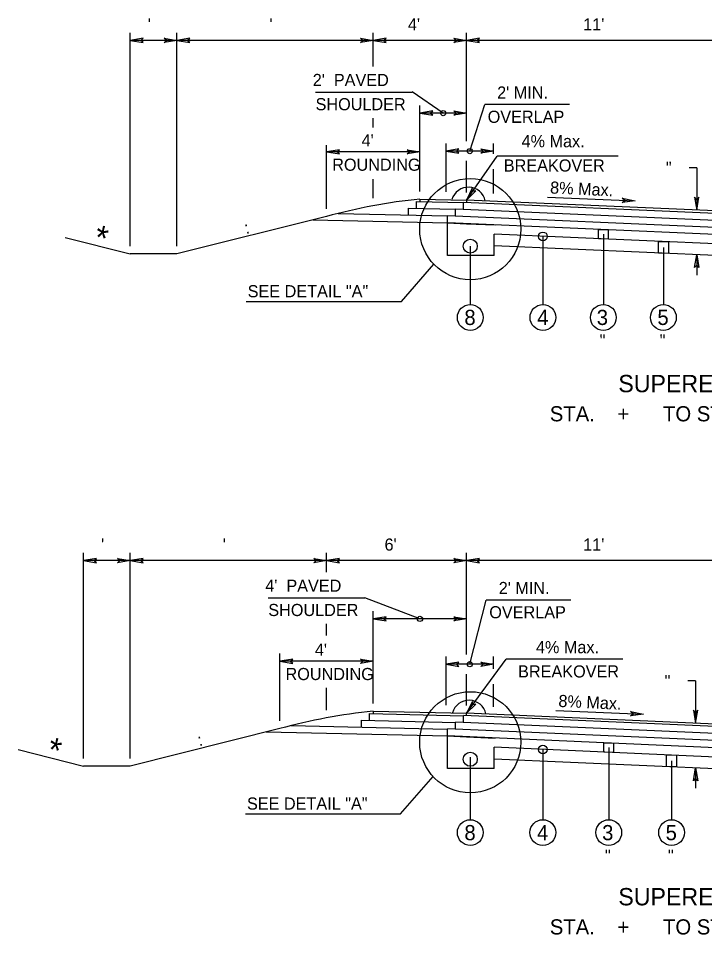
# Model space of a CAD drawing. Extents: x -592 to 1199, y -590 to 416.
# Drawn here: x 735.1 to 814.3, y 160.9 to 266.7 of the extents above; entities that cross this region are included whole.
import ezdxf

# ---------------------------------------------------------------- set-up
doc = ezdxf.new("R2010")
doc.units = 0
doc.layers.add('1', color=7, linetype='Continuous')
doc.layers.add('Des_ Drain_ Ftrs', color=7, linetype='Continuous')

msp = doc.modelspace()

# ---------------------------------------------------------------- linework, layer by layer
at = {"layer": '1'}
for p, q in [((747.99, 240.4), (747.99, 265.03)), ((753.38, 240.4), (753.38, 265.03)), ((776.04, 261.16), (776.04, 265.03)), ((786.81, 252.51), (786.81, 265.03)), ((753.38, 264.15), (747.99, 264.15)), ((776.04, 264.15), (753.38, 264.15)), ((786.81, 264.15), (776.04, 264.15)), ((816.45, 264.15), (786.81, 264.15)), ((769.38, 258.19), (780.52, 258.19)), ((784.12, 255.76), (780.53, 258.21)), ((781.43, 246.73), (781.43, 256.64)), ((787.18, 251.38), (788.92, 256.74)), ((798.68, 256.74), (788.92, 256.74)), ((776.04, 254.11), (776.04, 255.18)), ((786.81, 255.76), (781.43, 255.76)), ((770.65, 244.72), (770.65, 252.06)), ((784.44, 246.66), (784.44, 252.26)), ((789.92, 251.05), (789.92, 252.26)), ((781.43, 251.3), (770.65, 251.3)), ((789.92, 251.38), (784.44, 251.38)), ((786.81, 245.73), (790.36, 250.79)), ((804.31, 250.79), (790.36, 250.79)), ((786.81, 246.61), (786.81, 250.25)), ((789.92, 246.48), (789.92, 249.29)), ((813.39, 249.45), (812.51, 249.45)), ((813.39, 249.45), (813.39, 244.57)), ((776.04, 245.95), (776.04, 248.13)), ((781.04, 245.56), (786.47, 245.45)), ((781.04, 244.78), (781.04, 245.56)), ((781.43, 245.85), (786.81, 245.73)), ((781.43, 245.85), (781.43, 245.55)), ((816.45, 244.14), (786.47, 245.45)), ((786.47, 244.64), (786.47, 245.45)), ((816.45, 244.44), (786.81, 245.73)), ((786.81, 245.73), (786.81, 245.43)), ((796.15, 246.08), (806.26, 245.64)), ((780.11, 244.8), (785.55, 244.68)), ((780.11, 244.01), (780.11, 244.8)), ((816.45, 243.33), (785.55, 244.68)), ((785.55, 243.87), (785.55, 244.68)), ((770.65, 243.84), (753.38, 239.52)), ((769.06, 243.44), (784.62, 243.1)), ((771.97, 244.18), (784.62, 243.91)), ((816.45, 242.52), (784.62, 243.91)), ((784.62, 243.1), (784.62, 243.91)), ((784.62, 239.34), (784.62, 243.1)), ((784.62, 243.1), (786.81, 243)), ((816.45, 241.71), (784.64, 243.1)), ((786.81, 243), (790.11, 242.86)), ((740.46, 241.4), (747.99, 239.52)), ((816.45, 240.63), (790.01, 241.79)), ((790.01, 239.34), (790.01, 241.79)), ((795.63, 241.54), (795.63, 233.67)), ((802.6, 241.78), (802.6, 233.67)), ((787.24, 240.65), (787.24, 240.65)), ((787.24, 240.41), (787.24, 233.67)), ((816.45, 239.28), (790.01, 240.44)), ((809.53, 240.26), (809.53, 233.67)), ((753.38, 239.52), (747.99, 239.52)), ((790.01, 239.34), (784.62, 239.34)), ((813.39, 239.42), (813.39, 237.05)), ((779.29, 234.01), (783.02, 238.33)), ((761.35, 234.01), (779.29, 234.01)), ((742.6, 181.29), (742.6, 205)), ((747.98, 204.12), (742.6, 204.12)), ((747.98, 181.29), (747.98, 205)), ((770.65, 204.12), (747.98, 204.12)), ((770.65, 202.79), (770.65, 205)), ((786.81, 204.12), (770.65, 204.12)), ((786.81, 193.29), (786.81, 205)), ((816.45, 204.12), (786.81, 204.12)), ((763.92, 199.82), (775.06, 199.82)), ((781.43, 197.39), (775.06, 199.82)), ((787.18, 192.16), (789.09, 199.56)), ((798.86, 199.56), (789.09, 199.56)), ((776.04, 187.63), (776.04, 198.27)), ((770.65, 195.47), (770.65, 196.83)), ((786.81, 197.39), (776.04, 197.39)), ((765.26, 185.62), (765.26, 193.39)), ((776.04, 192.51), (765.26, 192.51)), ((784.44, 187.44), (784.44, 193.04)), ((786.81, 186.51), (791.39, 192.73)), ((789.92, 191.62), (789.92, 193.04)), ((804.87, 192.73), (791.39, 192.73)), ((789.92, 192.16), (784.44, 192.16)), ((786.81, 187.39), (786.81, 191.03)), ((770.65, 186.85), (770.65, 189.45)), ((789.92, 187.25), (789.92, 189.85)), ((813.25, 190.24), (812.37, 190.24)), ((813.25, 190.24), (813.25, 185.36)), ((775.61, 186.46), (786.46, 186.22)), ((775.61, 185.67), (775.61, 186.46)), ((776.04, 186.75), (786.81, 186.51)), ((776.04, 186.75), (776.04, 186.45)), ((816.45, 184.92), (786.47, 186.23)), ((786.47, 185.42), (786.47, 186.23)), ((816.45, 185.22), (786.81, 186.51)), ((786.81, 186.21), (786.81, 186.51)), ((797.11, 186.82), (807.22, 186.38)), ((766.56, 185.08), (784.58, 184.68)), ((774.68, 185.69), (785.52, 185.45)), ((774.68, 184.9), (774.68, 185.69)), ((816.45, 184.11), (785.55, 185.46)), ((785.55, 184.65), (785.55, 185.46)), ((765.26, 184.74), (747.98, 180.41)), ((763.67, 184.34), (784.62, 183.88)), ((816.45, 183.3), (784.62, 184.69)), ((784.62, 183.88), (784.62, 184.69)), ((816.45, 182.49), (784.62, 183.88)), ((784.62, 180.12), (784.62, 183.88)), ((784.62, 183.88), (786.81, 183.78)), ((786.81, 183.78), (790.11, 183.64)), ((735.06, 182.3), (742.6, 180.41)), ((816.45, 181.41), (790.01, 182.57)), ((790.01, 180.12), (790.01, 182.57)), ((795.62, 182.32), (795.62, 174.21)), ((803.22, 182.56), (803.22, 174.21)), ((787.24, 181.43), (787.24, 181.43)), ((787.24, 181.43), (787.24, 174.21)), ((816.45, 180.06), (790.01, 181.22)), ((810.48, 181), (810.48, 174.21)), ((747.98, 180.41), (742.6, 180.41)), ((790.01, 180.12), (784.62, 180.12)), ((813.25, 180.2), (813.25, 177.84)), ((779.2, 174.88), (782.94, 179.2)), ((761.27, 174.88), (779.2, 174.88))]:
    msp.add_line(p, q, dxfattribs=at)
for points in [[(802.03, 242.34), (803.17, 242.29), (803.17, 241.21), (802.03, 241.26)], [(808.96, 240.96), (810.11, 240.91), (810.11, 239.56), (808.96, 239.61)], [(802.64, 183.09), (803.79, 183.04), (803.79, 181.96), (802.64, 182.01)], [(809.91, 181.7), (811.06, 181.65), (811.06, 180.3), (809.91, 180.35)]]:
    msp.add_lwpolyline(points, close=True, dxfattribs=at)
for centre, radius in [((784.12, 255.76), 0.3), ((787.18, 251.38), 0.3), ((787.24, 242.37), 5.84), ((787.24, 240.41), 0.808), ((795.63, 241.54), 0.5), ((787.24, 232.18), 1.49), ((795.63, 232.18), 1.49), ((802.6, 232.18), 1.49), ((809.53, 232.18), 1.49), ((781.43, 197.39), 0.3), ((787.18, 192.16), 0.3), ((787.24, 183.15), 5.84), ((787.24, 181.19), 0.808), ((795.62, 182.32), 0.5), ((787.24, 172.73), 1.49), ((795.62, 172.73), 1.49), ((803.22, 172.73), 1.49), ((810.48, 172.73), 1.49)]:
    msp.add_circle(centre, radius, dxfattribs=at)
for centre, radius, start, end in [((787.02, 245.21), 2, 12.2495, 163.1706), ((788.32, 179.01), 67.19, 95.8901, 105.2487), ((787.09, 186), 2, 12.083, 163.9225), ((782.93, 119.91), 67.19, 95.8911, 105.2497)]:
    msp.add_arc(centre, radius, start, end, dxfattribs=at)
at = {"layer": 'Des_ Drain_ Ftrs'}
for points in [[(747.99, 264.15), (749.48, 263.9), (749.19, 264.15), (749.48, 264.4)], [(753.38, 264.15), (751.89, 263.9), (752.19, 264.15), (751.89, 264.4)], [(753.38, 264.15), (754.87, 263.9), (754.57, 264.15), (754.87, 264.4)], [(776.04, 264.15), (774.55, 263.9), (774.84, 264.15), (774.55, 264.4)], [(776.04, 264.15), (777.53, 263.9), (777.23, 264.15), (777.53, 264.4)], [(786.81, 264.15), (785.33, 263.9), (785.62, 264.15), (785.33, 264.4)], [(786.81, 264.15), (788.3, 263.9), (788.01, 264.15), (788.3, 264.4)], [(781.43, 255.76), (782.91, 255.51), (782.62, 255.76), (782.91, 256.01)], [(786.81, 255.76), (785.33, 255.51), (785.62, 255.76), (785.33, 256.01)], [(770.65, 251.3), (772.14, 251.05), (771.84, 251.3), (772.14, 251.54)], [(781.43, 251.3), (779.94, 251.05), (780.23, 251.3), (779.94, 251.54)], [(784.44, 251.38), (785.93, 251.13), (785.63, 251.38), (785.93, 251.63)], [(789.92, 251.38), (788.44, 251.13), (788.73, 251.38), (788.44, 251.63)], [(786.81, 245.73), (787.87, 246.81), (787.5, 246.71), (787.46, 247.09)], [(806.26, 245.64), (804.76, 245.45), (805.07, 245.69), (804.79, 245.95)], [(813.39, 244.57), (813.64, 246.06), (813.39, 245.76), (813.14, 246.06)], [(813.39, 239.42), (813.64, 237.93), (813.39, 238.23), (813.14, 237.93)], [(742.6, 204.12), (744.08, 203.87), (743.79, 204.12), (744.08, 204.37)], [(747.98, 204.12), (746.5, 203.87), (746.79, 204.12), (746.5, 204.37)], [(747.98, 204.12), (749.47, 203.87), (749.18, 204.12), (749.47, 204.37)], [(770.65, 204.12), (769.16, 203.87), (769.46, 204.12), (769.16, 204.37)], [(770.65, 204.12), (772.14, 203.87), (771.84, 204.12), (772.14, 204.37)], [(786.81, 204.12), (785.33, 203.87), (785.62, 204.12), (785.33, 204.37)], [(786.81, 204.12), (788.3, 203.87), (788.01, 204.12), (788.3, 204.37)], [(776.04, 197.39), (777.53, 197.15), (777.23, 197.39), (777.53, 197.64)], [(786.81, 197.39), (785.33, 197.15), (785.62, 197.39), (785.33, 197.64)], [(765.26, 192.51), (766.75, 192.26), (766.45, 192.51), (766.75, 192.76)], [(776.04, 192.51), (774.55, 192.26), (774.84, 192.51), (774.55, 192.76)], [(784.44, 192.16), (785.93, 191.91), (785.63, 192.16), (785.93, 192.41)], [(789.92, 192.16), (788.44, 191.91), (788.73, 192.16), (788.44, 192.41)], [(786.81, 186.51), (787.89, 187.56), (787.52, 187.47), (787.49, 187.86)], [(807.22, 186.38), (805.72, 186.2), (806.03, 186.43), (805.75, 186.69)], [(813.25, 185.36), (813.5, 186.84), (813.25, 186.55), (813, 186.84)], [(813.25, 180.2), (813.5, 178.72), (813.25, 179.01), (813, 178.72)]]:
    msp.add_lwpolyline(points, close=True, dxfattribs=at)

# ---------------------------------------------------------------- texts
at = {"layer": '1'}
for s, height, p in [(" '", 1.4, (749.49, 265.3)), ("  '", 1.4, (763.01, 265.3)), ("4'", 1.4, (780.04, 265.3)), ("11'", 1.4, (800.28, 265.3)), ("2'  PAVED", 1.4, (769.05, 258.89)), ("2' MIN.", 1.4, (790.34, 257.44)), ('SHOULDER', 1.4, (769.38, 256.09)), ('OVERLAP', 1.4, (789.25, 254.64)), ("4'", 1.4, (774.69, 251.91)), ('4% Max.', 1.4, (793.16, 251.82)), ('ROUNDING', 1.4, (771.3, 249.11)), ('BREAKOVER', 1.4, (791.11, 249.02)), ('SEE DETAIL "A"', 1.4, (761.54, 234.51)), ('8', 1.75, (786.56, 231.31)), ('4', 1.75, (794.96, 231.31)), ('3', 1.75, (801.84, 231.31)), ('5', 1.75, (808.84, 231.31)), (' "', 1.4, (801.66, 228.82)), (' "', 1.4, (808.59, 228.82)), ('SUPERELEVATED', 2, (804.33, 223.55)), ('STA.    +      TO STA.    +     ', 1.75, (796.42, 220.19)), (" '", 1.4, (744.09, 205.27)), ("  '", 1.4, (757.62, 205.27)), ("6'", 1.4, (777.34, 205.27)), ("11'", 1.4, (800.28, 205.27)), ("4'  PAVED", 1.4, (763.57, 200.52)), ("2' MIN.", 1.4, (790.52, 200.26)), ('SHOULDER', 1.4, (763.92, 197.72)), ('OVERLAP', 1.4, (789.43, 197.46)), ('4% Max.', 1.4, (794.82, 193.43)), ("4'", 1.4, (769.3, 193.13)), ('ROUNDING', 1.4, (765.91, 190.33)), ('BREAKOVER', 1.4, (792.76, 190.63)), ('SEE DETAIL "A"', 1.4, (761.46, 175.38)), ('8', 1.75, (786.56, 171.85)), ('4', 1.75, (794.95, 171.85)), ('3', 1.75, (802.46, 171.85)), ('5', 1.75, (809.79, 171.85)), (' "', 1.4, (802.27, 169.37)), (' "', 1.4, (809.54, 169.37)), ('SUPERELEVATED', 2, (804.33, 164.33)), ('STA.    +      TO STA.    +     ', 1.75, (796.42, 160.97))]:
    msp.add_text(s, height=height, dxfattribs=at).set_placement(p)
for s, height, rotation, p in [('  "', 1.4, 0.1438, (808.78, 248.75)), ('8% Max.', 1.4, 357.3765, (796.43, 246.49)), ('*', 2.8, 347.1521, (743.62, 240.17)), (' : ', 1.4, 14.2282, (760.84, 241.67)), ('  "', 1.4, 0.1438, (808.64, 189.53)), ('8% Max.', 1.4, 357.3765, (797.39, 187.24)), ('*', 2.8, 347.1521, (738.23, 181.06)), (' : ', 1.4, 14.2282, (755.44, 182.56))]:
    msp.add_text(s, height=height, rotation=rotation, dxfattribs=at).set_placement(p)

doc.saveas('drawing.dxf')
